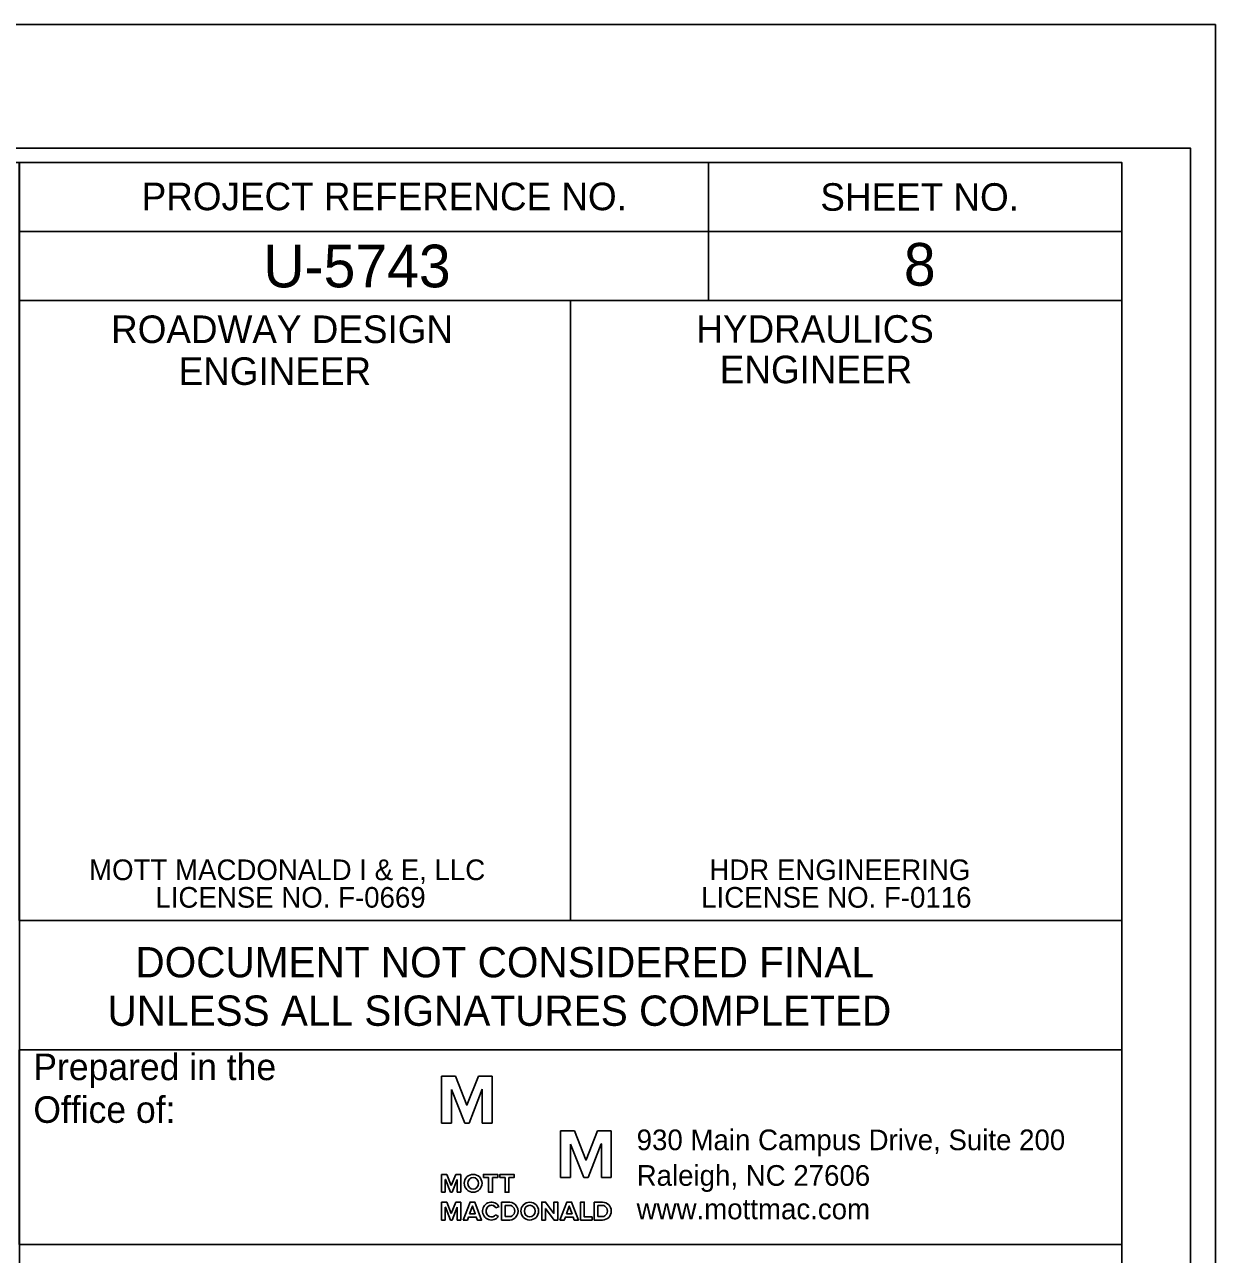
# Model space of a CAD drawing. Extents: x 1755181 to 1757273, y 729911 to 735411.
# Drawn here: x 1756648.6 to 1756864.7, y 735187.6 to 735410.8 of the extents above; entities that cross this region are included whole.
import ezdxf

# ---------------------------------------------------------------- set-up
doc = ezdxf.new("R2010")
doc.units = 0
for name, color, linetype in [('Old_Level_2', 7, 'Continuous'), ('Old_Level_3', 7, 'Continuous'), ('Old_Level_42', 7, 'Continuous'), ('Old_Level_45', 7, 'Continuous'), ('Sheet Cutting Line CELL', 7, 'Continuous'), ('Sheet Data Field CELL', 7, 'Continuous'), ('Sheet Plot Border Inside CELL', 7, 'Continuous'), ('Sheet Plot Border Outside CELL', 7, 'Continuous'), ('Sheet Profile CELL', 7, 'Continuous'), ('Sheet Profile Grid Major CELL', 7, 'Continuous'), ('Sheet Profile Grid Minor CELL', 7, 'Continuous'), ('Sheet Sticker Exception Certification CELL', 7, 'Continuous')]:
    doc.layers.add(name, color=color, linetype=linetype)

msp = doc.modelspace()

# ---------------------------------------------------------------- linework, layer by layer
at = {"layer": 'Old_Level_2'}
for p, q in [((1756726.76, 735219.94), (1756724.24, 735219.94)), ((1756724.24, 735219.94), (1756724.24, 735211.44)), ((1756728.81, 735214.69), (1756726.76, 735219.94)), ((1756730.92, 735219.94), (1756728.86, 735214.69)), ((1756733.44, 735219.94), (1756730.92, 735219.94)), ((1756733.44, 735211.44), (1756733.44, 735219.94)), ((1756726.03, 735211.44), (1756726.03, 735217.55)), ((1756726.03, 735217.55), (1756726.05, 735217.55)), ((1756726.05, 735217.55), (1756728.45, 735211.44)), ((1756729.23, 735211.44), (1756731.62, 735217.57)), ((1756731.62, 735217.57), (1756731.64, 735217.57)), ((1756731.64, 735217.57), (1756731.64, 735211.44)), ((1756728.81, 735214.61), (1756728.81, 735214.69)), ((1756728.86, 735214.61), (1756728.81, 735214.61)), ((1756728.86, 735214.69), (1756728.86, 735214.61)), ((1756724.24, 735211.44), (1756726.03, 735211.44)), ((1756728.45, 735211.44), (1756729.23, 735211.44)), ((1756731.64, 735211.44), (1756733.44, 735211.44)), ((1756748.37, 735210.04), (1756745.85, 735210.04)), ((1756745.85, 735210.04), (1756745.85, 735201.54)), ((1756750.42, 735204.78), (1756748.37, 735210.04)), ((1756752.53, 735210.04), (1756750.48, 735204.78)), ((1756755.05, 735210.04), (1756752.53, 735210.04)), ((1756755.05, 735201.54), (1756755.05, 735210.04)), ((1756747.64, 735201.54), (1756747.64, 735207.64)), ((1756747.64, 735207.64), (1756747.67, 735207.64)), ((1756747.67, 735207.64), (1756750.06, 735201.54)), ((1756750.84, 735201.54), (1756753.23, 735207.67)), ((1756753.23, 735207.67), (1756753.26, 735207.67)), ((1756753.26, 735207.67), (1756753.26, 735201.54)), ((1756750.42, 735204.71), (1756750.42, 735204.78)), ((1756750.48, 735204.71), (1756750.42, 735204.71)), ((1756750.48, 735204.78), (1756750.48, 735204.71)), ((1756725.2, 735202.13), (1756724.24, 735202.13)), ((1756724.24, 735202.13), (1756724.24, 735198.88)), ((1756724.91, 735198.88), (1756724.91, 735201.22)), ((1756724.91, 735201.22), (1756724.94, 735201.22)), ((1756724.91, 735201.22), (1756724.94, 735201.22)), ((1756724.94, 735201.22), (1756725.85, 735198.88)), ((1756726, 735200.1), (1756725.2, 735202.13)), ((1756726.81, 735202.13), (1756726, 735200.1)), ((1756726.16, 735198.88), (1756727.07, 735201.22)), ((1756727.77, 735202.13), (1756726.81, 735202.13)), ((1756727.07, 735201.22), (1756727.1, 735201.22)), ((1756727.07, 735201.22), (1756727.1, 735201.22)), ((1756727.07, 735201.22), (1756727.1, 735201.22)), ((1756727.1, 735201.22), (1756727.1, 735198.88)), ((1756727.77, 735198.88), (1756727.77, 735202.13)), ((1756727.77, 735198.88), (1756727.77, 735202.13)), ((1756745.85, 735201.54), (1756747.64, 735201.54)), ((1756750.06, 735201.54), (1756750.84, 735201.54)), ((1756753.26, 735201.54), (1756755.05, 735201.54)), ((1756724.24, 735198.88), (1756724.91, 735198.88)), ((1756725.85, 735198.88), (1756726.16, 735198.88)), ((1756727.1, 735198.88), (1756727.77, 735198.88)), ((1756725.2, 735197.09), (1756724.24, 735197.09)), ((1756724.24, 735197.09), (1756724.24, 735193.84)), ((1756726, 735195.06), (1756725.2, 735197.09)), ((1756726.81, 735197.09), (1756726, 735195.06)), ((1756727.77, 735197.09), (1756726.81, 735197.09)), ((1756727.77, 735193.84), (1756727.77, 735197.09)), ((1756736.61, 735197.09), (1756735.13, 735197.09)), ((1756735.13, 735197.09), (1756735.13, 735195.4)), ((1756735.8, 735194.46), (1756735.8, 735196.49)), ((1756735.8, 735196.49), (1756736.61, 735196.49)), ((1756751.94, 735197.09), (1756751.94, 735197.09)), ((1756753.43, 735197.09), (1756751.94, 735197.09)), ((1756751.94, 735197.09), (1756751.94, 735195.4)), ((1756752.62, 735194.46), (1756752.62, 735196.49)), ((1756752.62, 735196.49), (1756753.43, 735196.49)), ((1756724.91, 735193.84), (1756724.91, 735196.18)), ((1756724.91, 735196.18), (1756724.94, 735196.18)), ((1756724.94, 735196.18), (1756725.85, 735193.84)), ((1756726.16, 735193.84), (1756727.07, 735196.18)), ((1756727.07, 735196.18), (1756727.1, 735196.18)), ((1756727.1, 735196.18), (1756727.1, 735193.84)), ((1756734.6, 735194.51), (1756734.03, 735194.78)), ((1756734.6, 735194.51), (1756734.03, 735194.78)), ((1756734.11, 735196.03), (1756734.68, 735196.29)), ((1756734.11, 735196.03), (1756734.68, 735196.29)), ((1756735.13, 735195.4), (1756735.13, 735193.84)), ((1756736.61, 735194.46), (1756735.8, 735194.46)), ((1756751.94, 735195.4), (1756751.94, 735193.84)), ((1756753.43, 735194.46), (1756752.62, 735194.46)), ((1756753.43, 735196.47), (1756753.43, 735196.47)), ((1756724.24, 735193.84), (1756724.91, 735193.84)), ((1756725.85, 735193.84), (1756726.16, 735193.84)), ((1756727.1, 735193.84), (1756727.77, 735193.84)), ((1756735.13, 735193.84), (1756736.61, 735193.84)), ((1756751.94, 735193.84), (1756753.43, 735193.84))]:
    msp.add_line(p, q, dxfattribs=at)
for points in [[(1756731.85, 735201.54), (1756732.79, 735201.54), (1756732.79, 735198.88), (1756733.49, 735198.88), (1756733.49, 735201.54), (1756734.43, 735201.54), (1756734.43, 735202.13), (1756731.85, 735202.13), (1756731.85, 735201.54)], [(1756734.84, 735201.54), (1756735.78, 735201.54), (1756735.78, 735198.88), (1756736.48, 735198.88), (1756736.48, 735201.54), (1756737.41, 735201.54), (1756737.41, 735202.13), (1756734.84, 735202.13), (1756734.84, 735201.54)], [(1756728.16, 735193.84), (1756728.94, 735193.84), (1756729.15, 735194.39), (1756730.55, 735194.39), (1756730.76, 735193.84), (1756731.51, 735193.84), (1756730.27, 735197.09), (1756729.41, 735197.09), (1756728.16, 735193.84)], [(1756743.08, 735195.95), (1756743.11, 735195.95), (1756744.67, 735193.84), (1756745.32, 735193.84), (1756745.32, 735197.09), (1756744.64, 735197.09), (1756744.64, 735195.04), (1756743.11, 735197.09), (1756742.43, 735197.09), (1756742.43, 735193.84), (1756743.08, 735193.84), (1756743.08, 735195.95)], [(1756745.73, 735193.84), (1756746.51, 735193.84), (1756746.72, 735194.39), (1756748.12, 735194.39), (1756748.33, 735193.84), (1756749.09, 735193.84), (1756747.84, 735197.09), (1756746.98, 735197.09), (1756745.73, 735193.84)], [(1756751.56, 735193.84), (1756751.56, 735194.41), (1756750.15, 735194.41), (1756750.15, 735197.09), (1756749.48, 735197.09), (1756749.48, 735193.84), (1756751.56, 735193.84)], [(1756751.56, 735193.84), (1756751.56, 735194.41), (1756750.15, 735194.41), (1756750.15, 735197.09), (1756749.48, 735197.09), (1756749.48, 735193.84), (1756751.56, 735193.84), (1756751.56, 735194.41)], [(1756729.33, 735194.98), (1756729.85, 735196.39), (1756730.37, 735194.98), (1756729.33, 735194.98)], [(1756746.9, 735194.98), (1756747.42, 735196.39), (1756747.94, 735194.98), (1756746.9, 735194.98)]]:
    msp.add_lwpolyline(points, dxfattribs=at)
msp.add_arc((1756753.43, 735195.47), 1.62, 270, 90, dxfattribs=at)
for centre, major_axis, ratio in [((1756729.98, 735200.51), (0, 1.62), 0.993118), ((1756729.98, 735200.51), (0, 1.06), 0.916103), ((1756740.25, 735195.47), (0, 1.62), 0.993118), ((1756740.25, 735195.47), (0, 1.06), 0.916103)]:
    msp.add_ellipse(centre, major_axis=major_axis, ratio=ratio, dxfattribs=at)
for centre, major_axis, ratio, start_param, end_param in [((1756733.29, 735195.47), (0, 1.62), 0.993118, 5.246647, 10.366427), ((1756733.29, 735195.47), (0, 1.62), 0.993118, 5.246647, 10.366427), ((1756733.29, 735195.47), (0, 1.06), 0.916103, 5.276876, 9.424778), ((1756733.29, 735195.47), (0, 1.06), 0.916103, 5.276876, 10.296021), ((1756736.61, 735195.46), (0, -1.62), 0.930276, 0, 3.141593), ((1756736.61, 735195.48), (0, -1.01), 0.900832, 0, 3.141593), ((1756753.43, 735195.48), (0, -1.01), 0.900832, 0, 3.141593), ((1756733.29, 735195.47), (0, 1.06), 0.916103, 3.141593, 4.012835)]:
    msp.add_ellipse(centre, major_axis=major_axis, ratio=ratio, start_param=start_param, end_param=end_param, dxfattribs=at)
at = {"layer": 'Old_Level_42'}
msp.add_lwpolyline([(1756847.67, 735189.43), (1756647.62, 735189.43), (1756647.62, 735224.73)], dxfattribs=at)
at = {"layer": 'Sheet Cutting Line CELL'}
msp.add_line((1756864.67, 735410.78), (1755180.67, 735410.78), dxfattribs=at)
at = {"layer": 'Sheet Plot Border Inside CELL'}
msp.add_lwpolyline([(1755193.67, 734333.23), (1756860.17, 734333.23), (1756860.17, 735388.33), (1755193.67, 735388.33)], close=True, dxfattribs=at)
at = {"layer": 'Sheet Plot Border Outside CELL'}
msp.add_lwpolyline([(1755180.67, 734310.78), (1756864.67, 734310.78), (1756864.67, 735410.78), (1755180.67, 735410.78)], close=True, dxfattribs=at)
at = {"layer": 'Sheet Profile CELL'}
for p, q in [((1756772.67, 735385.73), (1756772.67, 735360.73)), ((1756647.62, 735373.23), (1756847.67, 735373.23)), ((1756747.67, 735360.73), (1756747.67, 735248.28))]:
    msp.add_line(p, q, dxfattribs=at)
for points in [[(1756847.67, 735385.78), (1755347.67, 735385.78), (1755347.67, 734335.78), (1756847.67, 734335.78)], [(1756647.62, 735385.78), (1756847.67, 735385.78), (1756847.67, 735360.73), (1756647.62, 735360.73)], [(1756647.62, 735360.73), (1756747.67, 735360.73), (1756747.67, 735248.23), (1756647.62, 735248.23)], [(1756747.67, 735360.73), (1756847.67, 735360.73), (1756847.67, 735248.23), (1756747.67, 735248.23)]]:
    msp.add_lwpolyline(points, close=True, dxfattribs=at)
at = {"layer": 'Sheet Profile Grid Major CELL'}
for points in [[(1756197.67, 734885.78), (1756247.67, 734885.78), (1756247.67, 735385.78), (1756297.67, 735385.78), (1756297.67, 734885.78), (1756347.67, 734885.78), (1756347.67, 735385.78), (1756397.67, 735385.78), (1756397.67, 734885.78), (1756447.67, 734885.78), (1756447.67, 735385.78), (1756497.67, 735385.78), (1756497.67, 734885.78), (1756547.67, 734885.78), (1756547.67, 735385.78), (1756597.67, 735385.78), (1756597.67, 734885.78), (1756647.67, 734885.78), (1756647.67, 735385.78), (1756673.97, 735385.78)], [(1756797.67, 735152.66), (1756797.67, 734885.78), (1756847.67, 734885.78), (1756847.67, 735235.78)]]:
    msp.add_lwpolyline(points, dxfattribs=at)
at = {"layer": 'Sheet Profile Grid Minor CELL'}
msp.add_lwpolyline([(1756642.67, 735385.78), (1756652.67, 735385.78)], dxfattribs=at)
at = {"layer": 'Sheet Sticker Exception Certification CELL'}
for p, q in [((1756647.62, 735248.23), (1756847.66, 735248.23)), ((1756847.66, 735248.22), (1756847.66, 735224.72)), ((1756847.66, 735224.73), (1756647.62, 735224.73))]:
    msp.add_line(p, q, dxfattribs=at)

# ---------------------------------------------------------------- texts
at = {"layer": 'Old_Level_2'}
for s, height, p in [('Prepared in the ', 4.8186, (1756650.17, 735219.23)), ('Office of:', 4.819, (1756650.17, 735211.48))]:
    msp.add_text(s, height=height, dxfattribs=at).set_placement(p)
for s, p in [('930 Main Campus Drive, Suite 200', (1756759.65, 735206.52)), ('Raleigh, NC 27606', (1756759.65, 735200.06)), ('www.mottmac.com', (1756759.65, 735193.98))]:
    msp.add_text(s, height=3.75, rotation=360, dxfattribs=at).set_placement(p)
at = {"layer": 'Old_Level_3'}
for s, p in [('HDR ENGINEERING', (1756772.84, 735255.53)), (' LICENSE NO. F-0116', (1756769.97, 735250.53))]:
    msp.add_text(s, height=3.75, rotation=360, dxfattribs=at).set_placement(p)
at = {"layer": 'Old_Level_45'}
for s, p in [('MOTT MACDONALD I & E, LLC', (1756660.28, 735255.53)), (' LICENSE NO. F-0669', (1756670.92, 735250.53))]:
    msp.add_text(s, height=3.75, rotation=360, dxfattribs=at).set_placement(p)
at = {"layer": 'Sheet Data Field CELL'}
for s, p in [('U-5743', (1756691.91, 735363.1)), ('8', (1756808.14, 735363.4))]:
    msp.add_text(s, height=7.75, dxfattribs=at).set_placement(p)
at = {"layer": 'Sheet Profile CELL'}
for s, height, p in [('PROJECT REFERENCE NO.', 5.0001, (1756669.83, 735377.1)), ('SHEET NO.', 5, (1756792.98, 735377)), ('ROADWAY DESIGN', 5.0001, (1756664.28, 735353)), ('HYDRAULICS', 5, (1756770.48, 735353.05)), ('ENGINEER', 5, (1756676.53, 735345.4)), ('ENGINEER', 5, (1756774.73, 735345.7))]:
    msp.add_text(s, height=height, dxfattribs=at).set_placement(p)
at = {"layer": 'Sheet Sticker Exception Certification CELL'}
for s, p in [('DOCUMENT NOT CONSIDERED FINAL', (1756668.69, 735237.89)), ('UNLESS ALL SIGNATURES COMPLETED', (1756663.62, 735229.09))]:
    msp.add_text(s, height=5.5, dxfattribs=at).set_placement(p)

doc.saveas('drawing.dxf')
